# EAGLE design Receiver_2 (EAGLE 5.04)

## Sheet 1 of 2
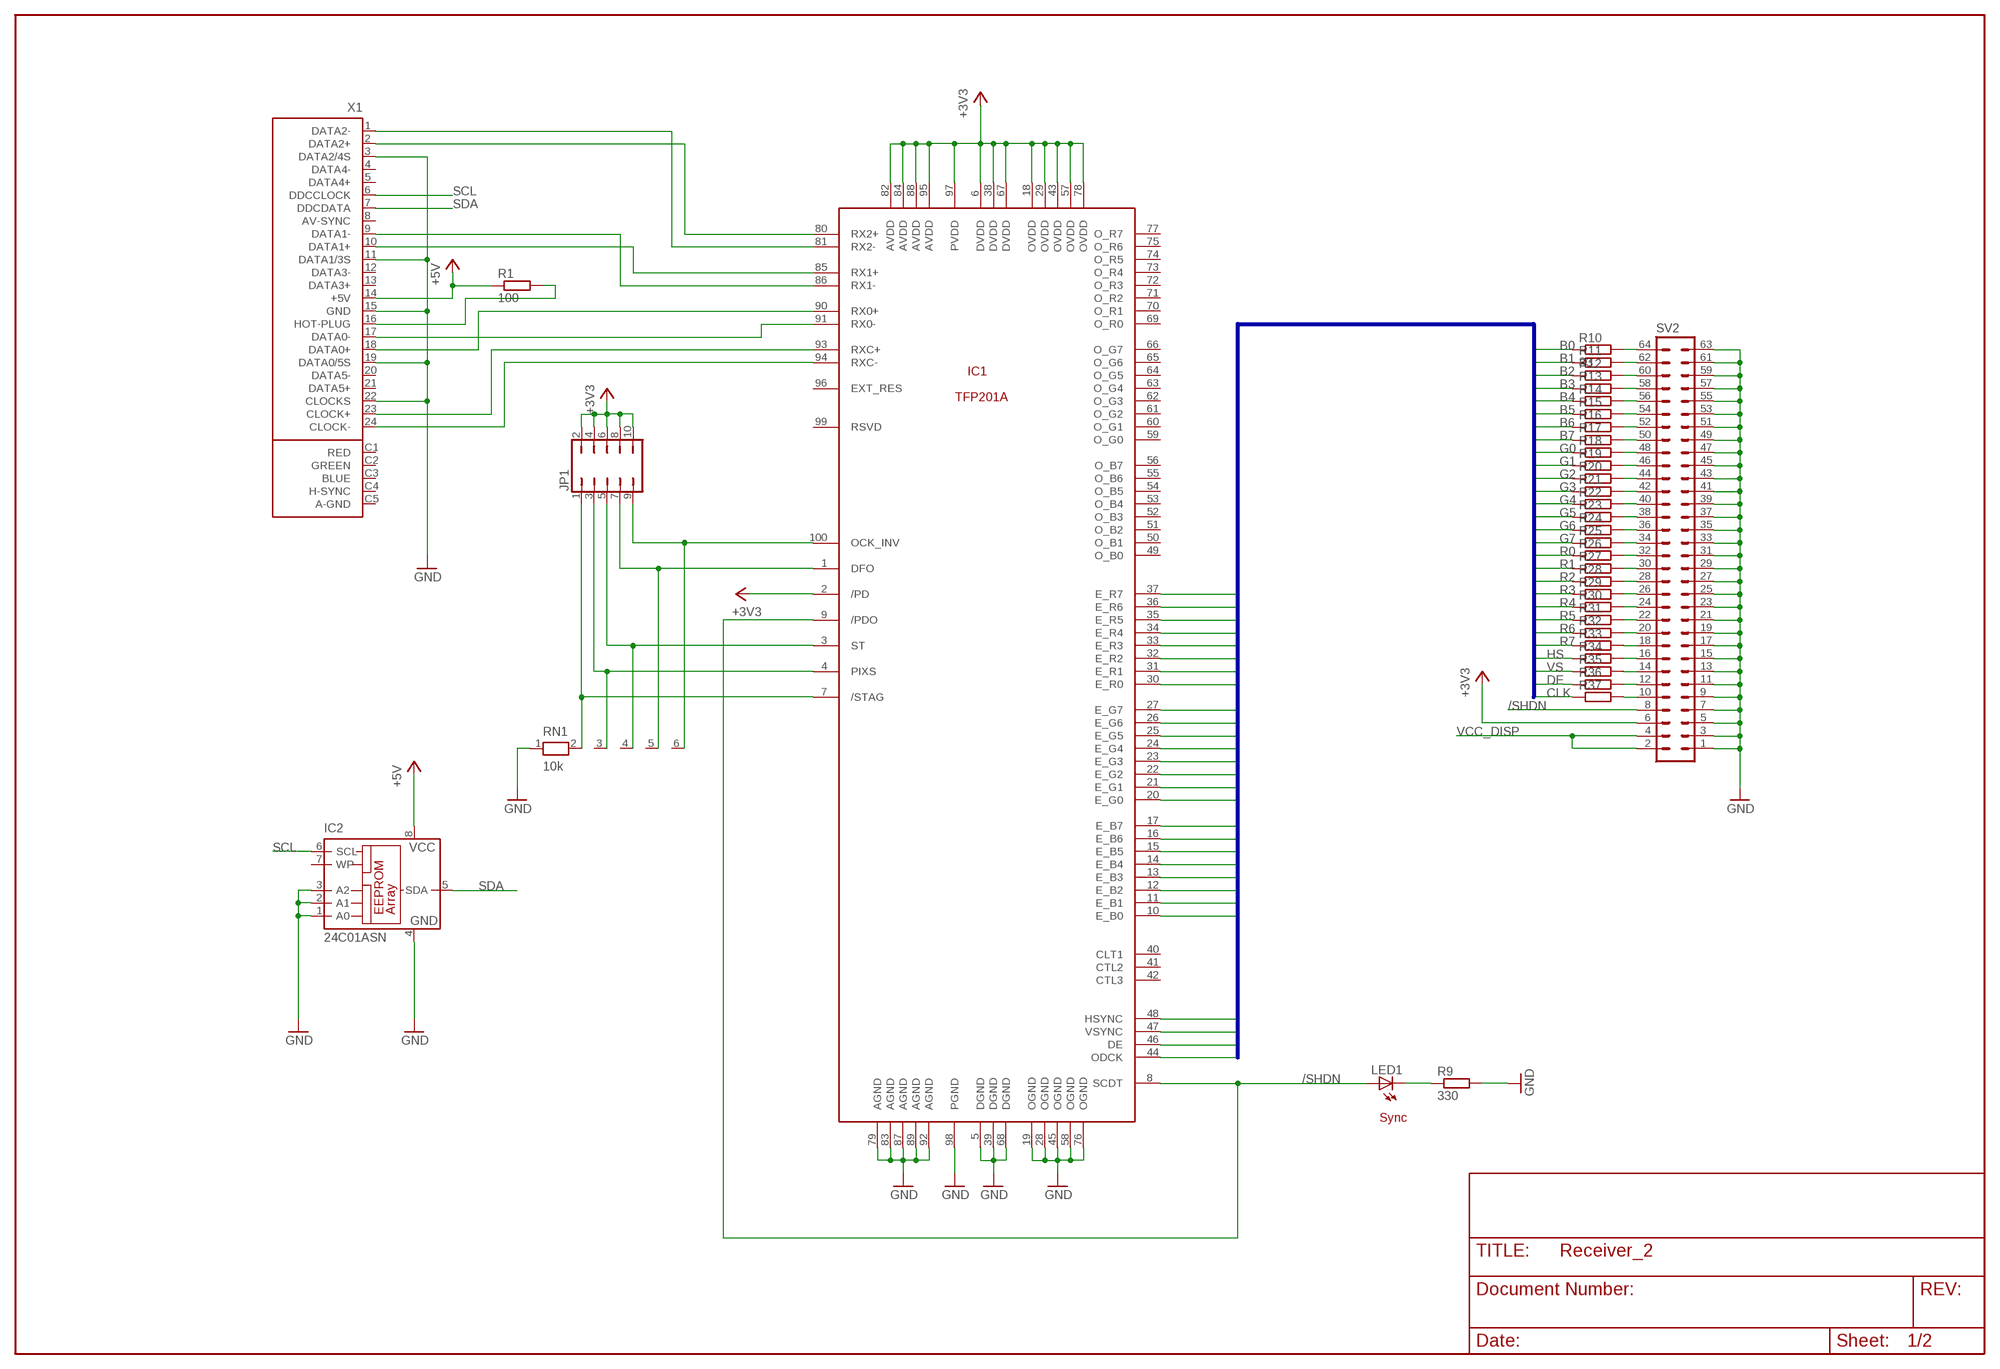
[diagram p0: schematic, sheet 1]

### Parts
IC1  TFP201ATQ100  [TQ100]
IC2  24C01ASN  [SO-08]
JP1  JP5Q  [JP5Q]
LED1  LEDCHIP-LED0805  [CHIP-LED0805]
R1  100  R-EU_R0805  [R0805]
R9  330  R-EU_R0805  [R0805]
R10  33  R-EU_R0805  [R0805]
R11  R-EU_R0805  [R0805]
R12  R-EU_R0805  [R0805]
R13  R-EU_R0805  [R0805]
R14  R-EU_R0805  [R0805]
R15  R-EU_R0805  [R0805]
R16  R-EU_R0805  [R0805]
R17  R-EU_R0805  [R0805]
R18  R-EU_R0805  [R0805]
R19  R-EU_R0805  [R0805]
R20  R-EU_R0805  [R0805]
R21  R-EU_R0805  [R0805]
R22  R-EU_R0805  [R0805]
R23  R-EU_R0805  [R0805]
R24  R-EU_R0805  [R0805]
R25  R-EU_R0805  [R0805]
R26  R-EU_R0805  [R0805]
R27  R-EU_R0805  [R0805]
R28  R-EU_R0805  [R0805]
R29  R-EU_R0805  [R0805]
R30  R-EU_R0805  [R0805]
R31  R-EU_R0805  [R0805]
R32  R-EU_R0805  [R0805]
R33  R-EU_R0805  [R0805]
R34  R-EU_R0805  [R0805]
R35  R-EU_R0805  [R0805]
R36  R-EU_R0805  [R0805]
R37  R-EU_R0805  [R0805]
RN1  10k  RN05  [RN-6]
SV2  ML64  [ML64]
X1  DVI-I-R  [DVI-I-R]

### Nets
+3V3: IC1.2(/PD) IC1.6(DVDD) IC1.18(OVDD) IC1.29(OVDD) IC1.38(DVDD) IC1.43(OVDD) IC1.57(OVDD) IC1.67(DVDD) IC1.78(OVDD) IC1.82(AVDD) IC1.84(AVDD) IC1.88(AVDD) IC1.95(AVDD) IC1.97(PVDD) JP1.2 JP1.4 JP1.6 JP1.8 JP1.10 SV2.6 ; also sheet 2
+5V: IC2.8(VCC) R1.1 X1.14(+5V)
/SHDN: IC1.8(SCDT) IC1.9(/PDO) LED1.A SV2.8 ; also sheet 2
B0: IC1.10(E_B0) R10.1
B1: IC1.11(E_B1) R11.1
B2: IC1.12(E_B2) R12.1
B3: IC1.13(E_B3) R13.1
B4: IC1.14(E_B4) R14.1
B5: IC1.15(E_B5) R15.1
B6: IC1.16(E_B6) R16.1
B7: IC1.17(E_B7) R17.1
CLK: IC1.44(ODCK) R37.1
DE: IC1.46(DE) R36.1
G0: IC1.20(E_G0) R18.1
G1: IC1.21(E_G1) R19.1
G2: IC1.22(E_G2) R20.1
G3: IC1.23(E_G3) R21.1
G4: IC1.24(E_G4) R22.1
G5: IC1.25(E_G5) R23.1
G6: IC1.26(E_G6) R24.1
G7: IC1.27(E_G7) R25.1
GND: IC1.5(DGND) IC1.19(OGND) IC1.28(OGND) IC1.39(DGND) IC1.45(OGND) IC1.58(OGND) IC1.68(DGND) IC1.76(OGND) IC1.79(AGND) IC1.83(AGND) IC1.87(AGND) IC1.89(AGND) IC1.92(AGND) IC1.98(PGND) IC2.1(A0) IC2.2(A1) IC2.3(A2) IC2.4(GND) R9.2 RN1.1 SV2.1 SV2.3 SV2.5 SV2.7 SV2.9 SV2.11 SV2.13 SV2.15 SV2.17 SV2.19 SV2.21 SV2.23 SV2.25 SV2.27 SV2.29 SV2.31 SV2.33 SV2.35 SV2.37 SV2.39 SV2.41 SV2.43 SV2.45 SV2.47 SV2.49 SV2.51 SV2.53 SV2.55 SV2.57 SV2.59 SV2.61 SV2.63 X1.3(DATA2/4S) X1.11(DATA1/3S) X1.15(GND) X1.19(DATA0/5S) X1.22(CLOCKS) ; also sheet 2
HS: IC1.48(HSYNC) R34.1
N$1: IC1.94(RXC-) X1.24(CLOCK-)
N$2: IC1.93(RXC+) X1.23(CLOCK+)
N$3: IC1.90(RX0+) X1.18(DATA0+)
N$4: IC1.91(RX0-) X1.17(DATA0-)
N$5: IC1.85(RX1+) X1.10(DATA1+)
N$6: IC1.86(RX1-) X1.9(DATA1-)
N$7: IC1.80(RX2+) X1.2(DATA2+)
N$8: IC1.81(RX2-) X1.1(DATA2-)
N$9: R10.2 SV2.64
N$13: R1.2 X1.16(HOT-PLUG)
N$15: IC1.100(OCK_INV) JP1.9 RN1.6
N$16: IC1.1(DFO) JP1.7 RN1.5
N$17: IC1.3(ST) JP1.5 RN1.4
N$19: IC1.4(PIXS) JP1.3 RN1.3
N$20: IC1.7(/STAG) JP1.1 RN1.2
N$22: LED1.C R9.1
N$24: R11.2 SV2.62
N$26: R12.2 SV2.60
N$27: R13.2 SV2.58
N$28: R14.2 SV2.56
N$30: R15.2 SV2.54
N$31: R16.2 SV2.52
N$32: R17.2 SV2.50
N$33: R18.2 SV2.48
N$34: R19.2 SV2.46
N$35: R20.2 SV2.44
N$36: R21.2 SV2.42
N$37: R22.2 SV2.40
N$38: R23.2 SV2.38
N$39: R24.2 SV2.36
N$40: R25.2 SV2.34
N$41: R26.2 SV2.32
N$42: R27.2 SV2.30
N$43: R28.2 SV2.28
N$44: R29.2 SV2.26
N$45: R30.2 SV2.24
N$46: R31.2 SV2.22
N$47: R32.2 SV2.20
N$48: R33.2 SV2.18
N$49: R34.2 SV2.16
N$50: R35.2 SV2.14
N$51: R36.2 SV2.12
N$52: R37.2 SV2.10
R0: IC1.30(E_R0) R26.1
R1: IC1.31(E_R1) R27.1
R2: IC1.32(E_R2) R28.1
R3: IC1.33(E_R3) R29.1
R4: IC1.34(E_R4) R30.1
R5: IC1.35(E_R5) R31.1
R6: IC1.36(E_R6) R32.1
R7: IC1.37(E_R7) R33.1
SCL: IC2.6(SCL) X1.6(DDCCLOCK)
SDA: IC2.5(SDA) X1.7(DDCDATA)
VCC_DISP: SV2.2 SV2.4 ; also sheet 2
VS: IC1.47(VSYNC) R35.1
Unconnected: IC1.40(CLT1) IC1.41(CTL2) IC1.42(CTL3) IC1.49(O_B0) IC1.50(O_B1) IC1.51(O_B2) IC1.52(O_B3) IC1.53(O_B4) IC1.54(O_B5) IC1.55(O_B6) IC1.56(O_B7) IC1.59(O_G0) IC1.60(O_G1) IC1.61(O_G2) IC1.62(O_G3) IC1.63(O_G4) IC1.64(O_G5) IC1.65(O_G6) IC1.66(O_G7) IC1.69(O_R0) IC1.70(O_R1) IC1.71(O_R2) IC1.72(O_R3) IC1.73(O_R4) IC1.74(O_R5) IC1.75(O_R6) IC1.77(O_R7) IC1.96(EXT_RES) IC1.99(RSVD) IC2.7(WP) X1.4(DATA4-) X1.5(DATA4+) X1.8(AV-SYNC) X1.12(DATA3-) X1.13(DATA3+) X1.20(DATA5-) X1.21(DATA5+) X1.C1(RED) X1.C2(GREEN) X1.C3(BLUE) X1.C4(H-SYNC)

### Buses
R[0..7],G[0..7],B[0..7],HS,VS,DE,CLK

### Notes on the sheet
- Sync

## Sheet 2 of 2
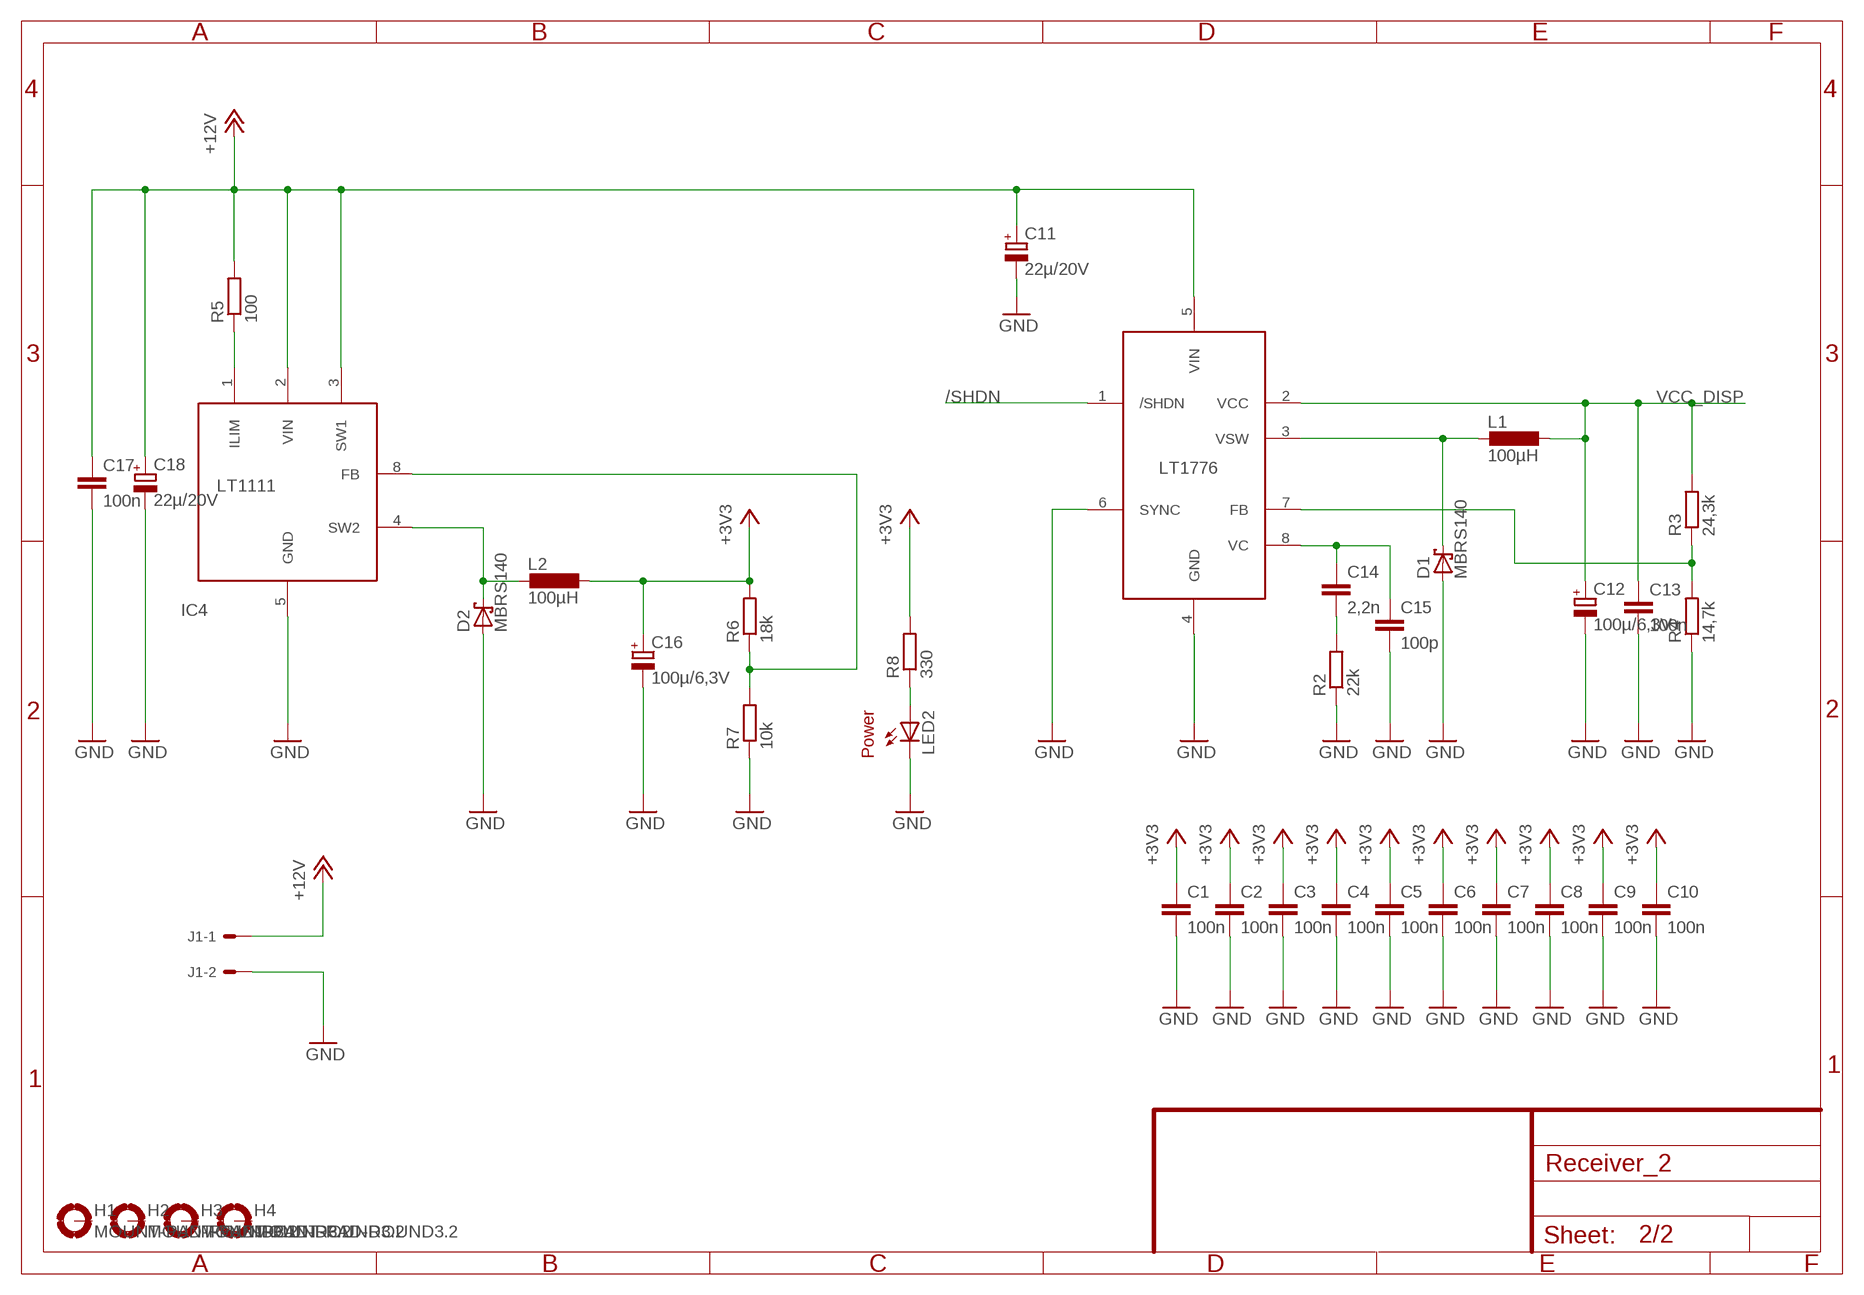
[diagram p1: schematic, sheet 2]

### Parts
C1  100n  C-EUC0805  [C0805]
C2  100n  C-EUC0805  [C0805]
C3  100n  C-EUC0805  [C0805]
C4  100n  C-EUC0805  [C0805]
C5  100n  C-EUC0805  [C0805]
C6  100n  C-EUC0805  [C0805]
C7  100n  C-EUC0805  [C0805]
C8  100n  C-EUC0805  [C0805]
C9  100n  C-EUC0805  [C0805]
C10  100n  C-EUC0805  [C0805]
C11  22µ/20V  CPOL-EUD/7343-31R  [D/7343-31R]
C12  100µ/6,3V  CPOL-EUD/7343-31R  [D/7343-31R]
C13  100n  C-EUC0805  [C0805]
C14  2,2n  C-EUC0805  [C0805]
C15  100p  C-EUC0805  [C0805]
C16  100µ/6,3V  CPOL-EUD/7343-31R  [D/7343-31R]
C17  100n  C-EUC0805  [C0805]
C18  22µ/20V  CPOL-EUD/7343-31R  [D/7343-31R]
D1  MBRS140  MBRS340  [SMC]
D2  MBRS140  MBRS340  [SMC]
H1  MOUNT-PAD-ROUND3.2  [3,2-PAD]
H2  MOUNT-PAD-ROUND3.2  [3,2-PAD]
H3  MOUNT-PAD-ROUND3.2  [3,2-PAD]
H4  MOUNT-PAD-ROUND3.2  [3,2-PAD]
IC3  LT1776CS8  [SO08]
IC4  LT1111CS  [SOIC8]
J1  22-27-2021-02  [6410-02]
L1  100µH  DO3316P  [DO3316P]
L2  100µH  DO3316P  [DO3316P]
LED2  LEDCHIP-LED0805  [CHIP-LED0805]
R2  22k  R-EU_R0805  [R0805]
R3  24,3k  R-EU_R0805  [R0805]
R4  14,7k  R-EU_R0805  [R0805]
R5  100  R-EU_R0805  [R0805]
R6  18k  R-EU_R0805  [R0805]
R7  10k  R-EU_R0805  [R0805]
R8  330  R-EU_R0805  [R0805]

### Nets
+3V3: C1.1 C2.1 C3.1 C4.1 C5.1 C6.1 C7.1 C8.1 C9.1 C10.1 C16.+ L2.2 R6.2 R8.2 ; also sheet 1
+12V: C11.+ C17.1 C18.+ IC3.5(VIN) IC4.2(VIN) IC4.3(SW1) J1.1 R5.2
/SHDN: IC3.1(/SHDN) ; also sheet 1
GND: C1.2 C2.2 C3.2 C4.2 C5.2 C6.2 C7.2 C8.2 C9.2 C10.2 C11.- C12.- C13.2 C15.2 C16.- C17.2 C18.- D1.A D2.A IC3.4(GND) IC3.6(SYNC) IC4.5(GND) J1.2 LED2.C R2.1 R4.1 R7.1 ; also sheet 1
N$10: IC3.7(FB) R3.1 R4.2
N$11: LED2.A R8.1
N$12: D1.C IC3.3(VSW) L1.1
N$14: C14.2 R2.2
N$18: IC4.1(ILIM) R5.1
N$21: C14.1 C15.1 IC3.8(VC)
N$25: D2.C IC4.4(SW2) L2.1
N$29: IC4.8(FB) R6.1 R7.2
VCC_DISP: C12.+ C13.1 IC3.2(VCC) L1.2 R3.2 ; also sheet 1
Unconnected: H1.B3,2(MOUNT) H2.B3,2(MOUNT) H3.B3,2(MOUNT) H4.B3,2(MOUNT)

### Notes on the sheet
- Power

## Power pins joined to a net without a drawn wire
A-GND: X1.C5(A-GND) X1.C6(A-GND)

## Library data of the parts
C1-C10 C13-C15 C17 = rcl:C-EU: CAPACITOR, European symbol
C11 C12 C16 C18 = rcl:CPOL-EU: POLARIZED CAPACITOR, European symbol
D1 D2 = diode:MBRS340
H1-H4 = holes:MOUNT-PAD-ROUND: MOUNTING PAD, round
IC1 = texas:TFP201A
IC2 = microchip:24C*: Serial EEPROM 1 K/2 K/4 K
IC3 = linear-technology:LT1776
IC4 = linear-technology:LT1111
J1 = con-molex_2:22-?-02: CONNECTOR
JP1 = jumper:JP5Q: JUMPER
L1 L2 = inductor-coilcraft:DO3316P: COILCRAFT
LED1 LED2 = led:LED: LED
R1-R37 = rcl:R-EU_: RESISTOR, European symbol
RN1 = resistor-net:RN05: RESISTOR NETWORK
SV2 = con-harting-ml:ML64: HARTING
X1 = con-molex:DVI-I-R: CONNECTOR MiroCross(TM)-DVI i/0 plug and receptacle connector system (scart)

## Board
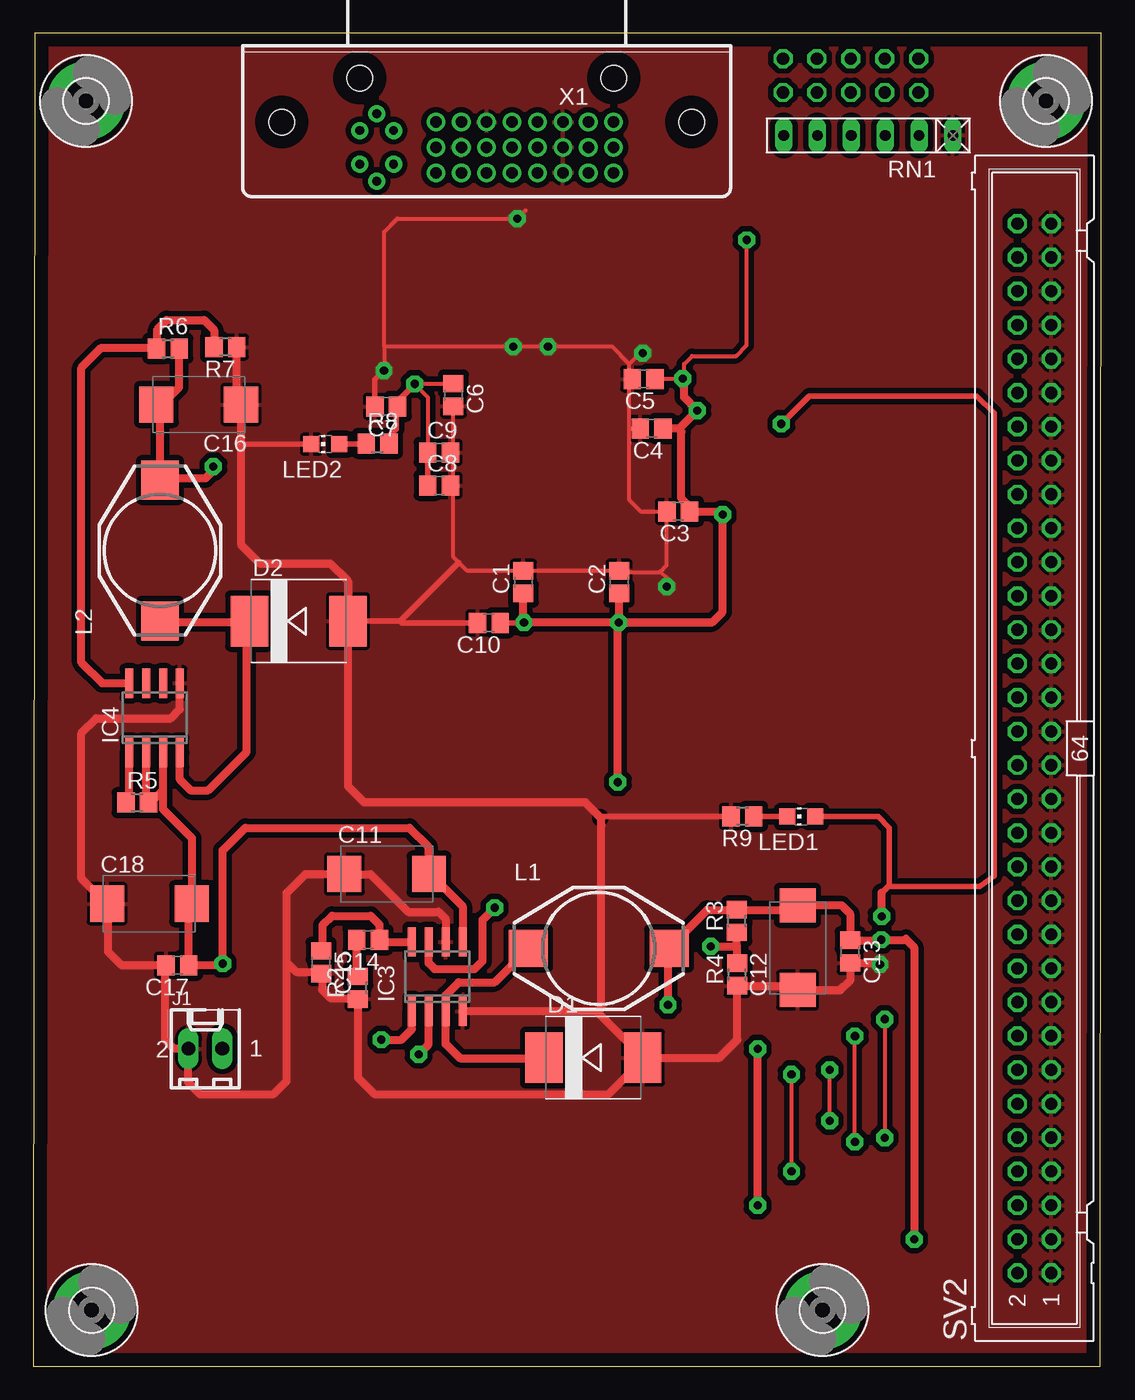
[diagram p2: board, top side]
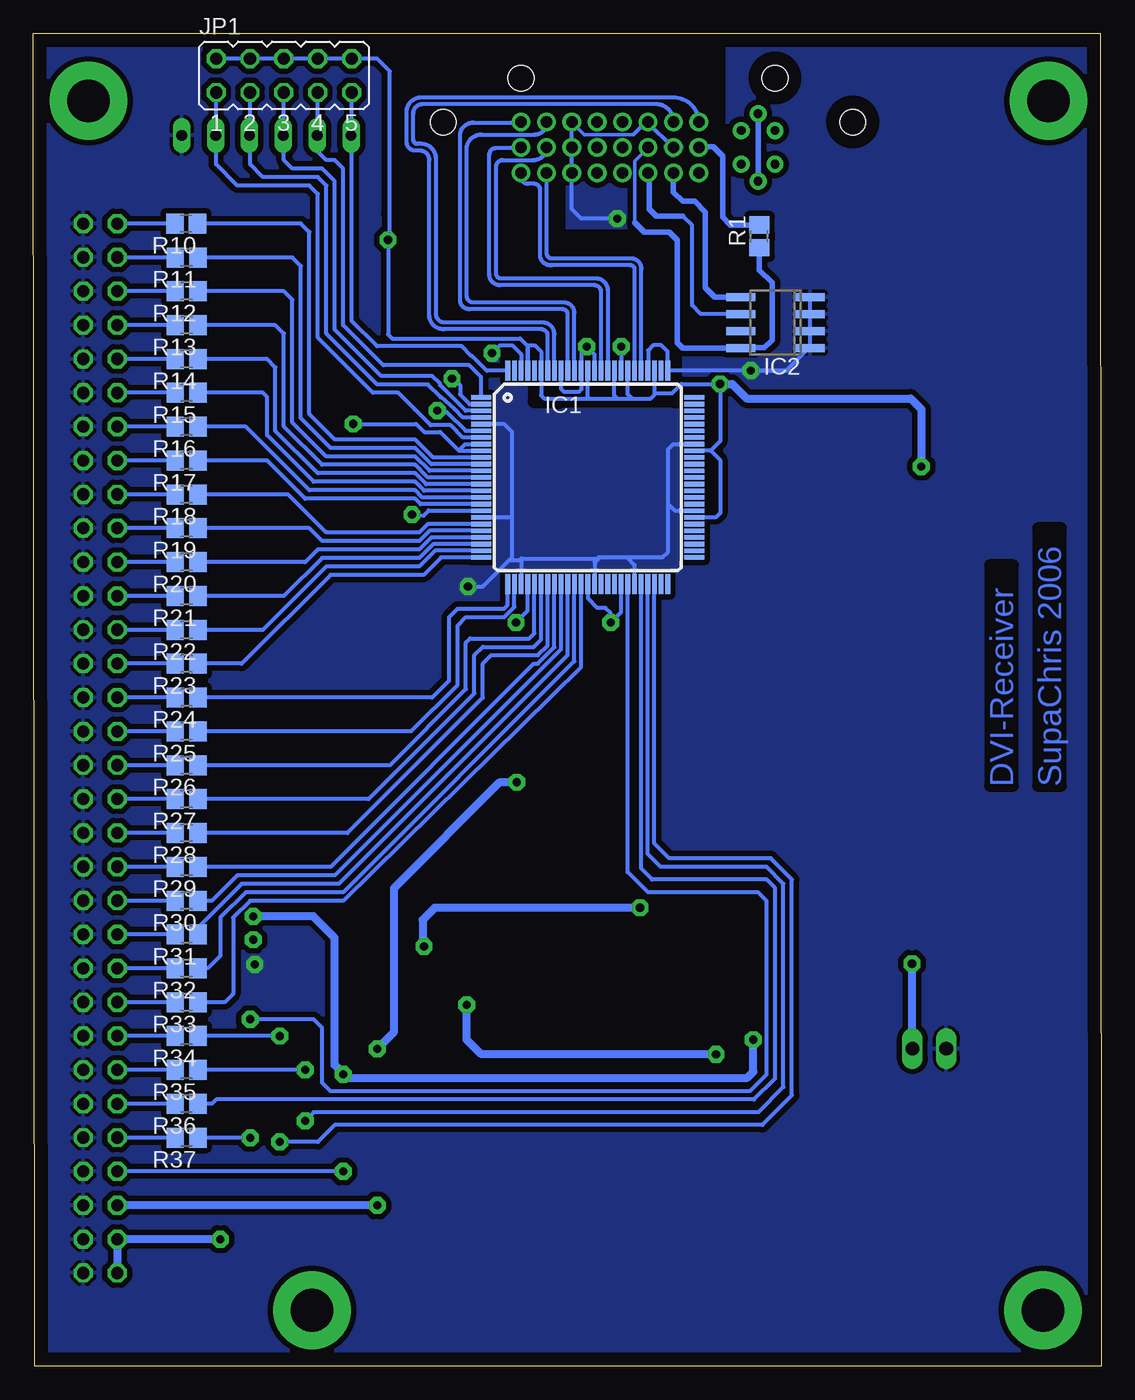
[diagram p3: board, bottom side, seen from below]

Size 80.1 x 100 mm. Coordinates in mm from the lower left corner, seen from the top.
Outline: 0.1,100 0,0 80,0 80.1,100 0.1,100
Copper layers (1+16): Top 0.035mm / dielectric 1.5mm / Bottom 0.035mm
Design rules "default": minimum track width 10mil, minimum drill 24mil, track to track 0.1mm, track to pad 0.1mm, pad to pad 0.1mm, via to via 0.2mm, smd to smd 0.1mm, copper to edge 40mil, drill to drill 8mil, minimum pad ring 10mil, minimum via ring 8mil, stop-mask expansion 4mil, vias tented up to drill 0mil, thermal gap 10mil
bRestrict: area 28.7,72.4 to 53.5,98.7; area 32,72.3 to 40.7,84.8

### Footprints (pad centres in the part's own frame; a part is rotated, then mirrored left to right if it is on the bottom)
C0805 = smd 1.3 x 1.5: 1 -0.85,0; 2 0.85,0
D/7343-31R = smd 2.55 x 2.7: + 3.175,0; - -3.175,0
SMC = smd 2.8 x 3.8: A 3.7,0; C -3.7,0
3,2-PAD = drill 3.2 pad 5.842 round: B3,2 0,0
TQ100 = smd 1.5 x 0.35: 1 -8,6; 2 -8,5.5; 3 -8,5; 4 -8,4.5; 5 -8,4; 6 -8,3.5; 7 -8,3; 8 -8,2.5; 9 -8,2; 10 -8,1.5; 11 -8,1; 12 -8,0.5; 13 -8,0; 14 -8,-0.5; 15 -8,-1; 16 -8,-1.5; 17 -8,-2; 18 -8,-2.5; 19 -8,-3; 20 -8,-3.5; 21 -8,-4; 22 -8,-4.5; 23 -8,-5; 24 -8,-5.5; 25 -8,-6; 51 8,-6; 52 8,-5.5; 53 8,-5; 54 8,-4.5; 55 8,-4; 56 8,-3.5; 57 8,-3; 58 8,-2.5; 59 8,-2; 60 8,-1.5; 61 8,-1; 62 8,-0.5; 63 8,0; 64 8,0.5; 65 8,1; 66 8,1.5; 67 8,2; 68 8,2.5; 69 8,3; 70 8,3.5; 71 8,4; 72 8,4.5; 73 8,5; 74 8,5.5; 75 8,6 | smd 0.35 x 1.5: 26 -6,-8; 27 -5.5,-8; 28 -5,-8; 29 -4.5,-8; 30 -4,-8; 31 -3.5,-8; 32 -3,-8; 33 -2.5,-8; 34 -2,-8; 35 -1.5,-8; 36 -1,-8; 37 -0.5,-8; 38 0,-8; 39 0.5,-8; 40 1,-8; 41 1.5,-8; 42 2,-8; 43 2.5,-8; 44 3,-8; 45 3.5,-8; 46 4,-8; 47 4.5,-8; 48 5,-8; 49 5.5,-8; 50 6,-8; 76 6,8; 77 5.5,8; 78 5,8; 79 4.5,8; 80 4,8; 81 3.5,8; 82 3,8; 83 2.5,8; 84 2,8; 85 1.5,8; 86 1,8; 87 0.5,8; 88 0,8; 89 -0.5,8; 90 -1,8; 91 -1.5,8; 92 -2,8; 93 -2.5,8; 94 -3,8; 95 -3.5,8; 96 -4,8; 97 -4.5,8; 98 -5,8; 99 -5.5,8; 100 -6,8
SO-08 = smd 0.6 x 2.2: 1 -1.905,-2.6; 2 -0.635,-2.6; 3 0.635,-2.6; 4 1.905,-2.6; 5 1.905,2.6; 6 0.635,2.6; 7 -0.635,2.6; 8 -1.905,2.6
SO08 = smd 0.6 x 2.2: 1 -1.905,-2.6; 2 -0.635,-2.6; 3 0.635,-2.6; 4 1.905,-2.6; 5 1.905,2.6; 6 0.635,2.6; 7 -0.635,2.6; 8 -1.905,2.6
SOIC8 = smd 0.6 x 2.2: 1 -1.905,-2.6; 2 -0.635,-2.6; 3 0.635,-2.6; 4 1.905,-2.6; 5 1.905,2.6; 6 0.635,2.6; 7 -0.635,2.6; 8 -1.905,2.6
6410-02 = drill 1.016 long: 1 1.27,0; 2 -1.27,0
JP5Q = drill 0.914 octagon: 1 -5.08,-1.27; 2 -5.08,1.27; 3 -2.54,-1.27; 4 -2.54,1.27; 5 0,-1.27; 6 0,1.27; 7 2.54,-1.27; 8 2.54,1.27; 9 5.08,-1.27; 10 5.08,1.27
DO3316P = smd 2.92 x 2.79: 1 -5.28,0; 2 5.28,0
CHIP-LED0805 = smd 1.2 x 1.2: A 0,-1.05; C 0,1.05
R0805 = smd 1.3 x 1.5: 1 -0.85,0; 2 0.85,0
RN-6 = drill 0.813 long: 1 -6.35,0; 2 -3.81,0; 3 -1.27,0; 4 1.27,0; 5 3.81,0; 6 6.35,0
ML64 = drill 0.914 octagon: 1 -39.37,-1.27; 2 -39.37,1.27; 3 -36.83,-1.27; 4 -36.83,1.27; 5 -34.29,-1.27; 6 -34.29,1.27; 7 -31.75,-1.27; 8 -31.75,1.27; 9 -29.21,-1.27; 10 -29.21,1.27; 11 -26.67,-1.27; 12 -26.67,1.27; 13 -24.13,-1.27; 14 -24.13,1.27; 15 -21.59,-1.27; 16 -21.59,1.27; 17 -19.05,-1.27; 18 -19.05,1.27; 19 -16.51,-1.27; 20 -16.51,1.27; 21 -13.97,-1.27; 22 -13.97,1.27; 23 -11.43,-1.27; 24 -11.43,1.27; 25 -8.89,-1.27; 26 -8.89,1.27; 27 -6.35,-1.27; 28 -6.35,1.27; 29 -3.81,-1.27; 30 -3.81,1.27; 31 -1.27,-1.27; 32 -1.27,1.27; 33 1.27,-1.27; 34 1.27,1.27; 35 3.81,-1.27; 36 3.81,1.27; 37 6.35,-1.27; 38 6.35,1.27; 39 8.89,-1.27; 40 8.89,1.27; 41 11.43,-1.27; 42 11.43,1.27; 43 13.97,-1.27; 44 13.97,1.27; 45 16.51,-1.27; 46 16.51,1.27; 47 19.05,-1.27; 48 19.05,1.27; 49 21.59,-1.27; 50 21.59,1.27; 51 24.13,-1.27; 52 24.13,1.27; 53 26.67,-1.27; 54 26.67,1.27; 55 29.21,-1.27; 56 29.21,1.27; 57 31.75,-1.27; 58 31.75,1.27; 59 34.29,-1.27; 60 34.29,1.27; 61 36.83,-1.27; 62 36.83,1.27; 63 39.37,-1.27; 64 39.37,1.27
DVI-I-R = drill 0.864 pad 1.397 round: 1 -9.525,6.985; 2 -7.62,6.985; 3 -5.715,6.985; 4 -3.81,6.985; 5 -1.905,6.985; 6 0,6.985; 7 1.905,6.985; 8 3.81,6.985; 9 -9.525,5.08; 10 -7.62,5.08; 11 -5.715,5.08; 12 -3.81,5.08; 13 -1.905,5.08; 14 0,5.08; 15 1.905,5.08; 16 3.81,5.08; 17 -9.525,3.175; 18 -7.62,3.175; 19 -5.715,3.175; 20 -3.81,3.175; 21 -1.905,3.175; 22 0,3.175; 23 1.905,3.175; 24 3.81,3.175 | drill 0.66 pad 1.27 round: C1 6.985,6.35; C2 9.525,6.35; C3 6.985,3.81; C4 9.525,3.81; C5 8.255,2.54; C6 8.255,7.62 | hole 1.93: -15.367,3.175; 15.367,3.175; -9.525,-0.127; 9.525,-0.127

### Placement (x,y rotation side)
C1  36.75,58.83 90 top
C2  43.94,58.83 90 top
C3  48.37,64.13 180 top
C4  46.37,70.35 180 top
C5  45.77,74.07 180 top
C6  31.51,72.87 270 top
C7  26.47,72.01 180 top
C8  30.43,66.07 0 top
C9  30.43,68.55 0 top
C10  34.17,55.77 180 top
C11  26.5,36.93 0 top
C12  57.33,31.4 90 top
C13  61.26,31.11 270 top
C14  25.11,32 180 top
C15  21.58,30.31 270 top
C16  12.4,72.16 180 top
C17  10.81,30.08 180 top
C18  8.7,34.7 0 top
D1  42,23.15 0 top
D2  19.9,55.9 0 top
H1  3.96,94.93 0 top
H2  75.96,94.93 0 top
H3  4.38,4.2 0 top
H4  59.2,4.2 0 top
IC1  38.52,66.68 0 bottom
IC2  24.45,78.3 90 bottom
IC3  30.29,29.23 0 top
IC4  9.09,48.64 0 top
J1  12.9,23.82 0 top
JP1  61.31,96.83 0 bottom
L1  42.4,31.35 0 top
L2  9.5,61.2 90 top
LED1  57.61,41.23 90 top
LED2  21.91,69.18 90 top
R1  25.65,84.77 90 bottom
R2  24.34,28.39 90 top
R3  52.76,33.39 90 top
R4  52.78,29.39 90 top
R5  7.79,42.28 0 top
R6  10.09,76.36 0 top
R7  14.41,76.46 180 top
R8  25.82,69.23 0 top
R9  53.18,41.26 180 top
R10  68.64,85.73 180 bottom
R11  68.61,83.19 180 bottom
R12  68.61,80.64 180 bottom
R13  68.61,78.11 180 bottom
R14  68.61,75.56 180 bottom
R15  68.61,73.03 180 bottom
R16  68.61,70.48 180 bottom
R17  68.61,67.94 180 bottom
R18  68.61,65.41 180 bottom
R19  68.61,62.87 180 bottom
R20  68.61,60.33 180 bottom
R21  68.61,57.78 180 bottom
R22  68.61,55.24 180 bottom
R23  68.61,52.7 180 bottom
R24  68.61,50.16 180 bottom
R25  68.61,47.62 180 bottom
R26  68.61,45.09 180 bottom
R27  68.61,42.55 180 bottom
R28  68.61,40.01 180 bottom
R29  68.61,37.47 180 bottom
R30  68.61,34.92 180 bottom
R31  68.61,32.38 180 bottom
R32  68.61,29.84 180 bottom
R33  68.61,27.3 180 bottom
R34  68.61,24.77 180 bottom
R35  68.61,22.23 180 bottom
R36  68.61,19.68 180 bottom
R37  68.61,17.14 180 bottom
RN1  62.62,92.34 180 top
SV2  75.08,46.36 90 top
X1  34,96.52 180 top

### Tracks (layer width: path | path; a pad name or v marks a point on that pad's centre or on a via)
+3V3  (via drill 0.61 pad 1.27)
  Top 0.305: 36.7,55.8 v36.8,55.8 36.75,55.85 | v53.5,84.5 53.5,76.6 52.7,75.8 49.4,75.8 48.8,75.2 48.8,74.1 | v43.9,55.8 43.94,55.84 | 49.5,64.2 v51.7,63.88 51.7,64.1 | 49.2,64.1 C3.1 | 48.8,74.1 v48.7,74.1 | 48.77,74.07 C5.1 | 48.77,74.07 48.8,74.1 | C9.1 29.58,72.72 v28.6,73.7 28.62,73.72 C6.1 | 48.45,70.35 48.4,70.35 48.4,70.3 48.6,70.1 | 48.77,74.07 48.77,74.03 48.8,74 | 48.8,74.1 48.7,74
  Top 0.406: v28.6,73.7 27.32,72.42 C7.1 27.21,72.01 27.2,72 27.2,70.3 26.67,69.77 R8.2 | C10.1 36.77,55.77 v36.8,55.8 | 29.55,68.55 29.5,68.6 | C9.1 29.55,68.55 | C8.1 29.58,68.52 29.55,68.55
  Top 0.61: v36.8,55.8 v43.9,55.8 50.9,55.8 | 49.5,64.2 48.6,65.1 48.6,70.1 | 50.9,55.8 51.7,56.6 51.7,64.1 49.2,64.1 | 36.75,55.85 C1.1 | 43.94,55.84 C2.1 | 48.4,70.35 C4.1 | 48.45,70.35 v49.8,71.7 48.8,72.7 48.8,74 | C16.+ 8.96,72.16 8.9,72.1 9.25,71.75 | 9.5,66.5 9.5,71.5 9.25,71.75 | R6.2 10.94,73.44 9.25,71.75 | v13.5,67.5 13.5,67.2 12.9,66.6 9.6,66.6 9.5,66.5 | 9.5,66.5 L2.2 | 43.84,55.8 50.9,55.8 | 43.84,55.8 43.84,55.88 | v43.84,43.81 43.84,55.8 | v54.32,12.06 v54.32,23.81 | 74.01,12.06 74,12.07 SV2.6
  Bottom 0.305: IC1.18 46.78,64.18 46.8,64.2 50.45,64.2 50.83,63.82 v51.7,63.88 | IC1.38 38.5,58.7 38.5,57.6 37.8,56.9 37.2,56.9 36.8,56.5 v36.8,55.8 36.02,56.58 IC1.43 | IC1.29 43.02,56.68 v43.9,55.8 | IC1.2 47.38,72.18 48.1,72.9 48.1,73.6 48.6,74.1 | 48.6,74.1 48.7,74.2 | 48.6,74.1 48.7,74 v48.7,74.1 | IC1.82 35.52,72.92 35.2,72.6 | 35.2,72.6 33.8,72.6 33.5,72.9 33.5,73 | IC1.78 33.52,74.62 33.5,74.6 33.5,73 | IC1.84 36.52,72.82 36.3,72.6 | 36.3,72.6 35.2,72.6 | IC1.88 38.52,72.72 38.4,72.6 | 38.4,72.6 36.3,72.6 | 38.4,72.6 41.8,72.6 42.02,72.82 IC1.95 42.02,76.12 42.5,76.6 43,76.6 43.02,76.58 IC1.97 43.02,76.52 43.6,77.1 53.2,77.1 53.5,77.4 53.5,84.4 53.55,84.45 v53.5,84.5 53.41,84.5 53.37,84.45 53.37,97.16 54.31,98.1 JP1.10 | 33.5,73 32.2,73 31.5,73.7 v28.6,73.7 28.6,69.4 29.3,68.7 | IC1.67 29.32,68.68 29.3,68.7 | IC1.57 28.92,63.68 28.6,64 28.6,68 29.3,68.7 | IC1.6 47.68,70.18 49.1,71.6 49.8,71.6 v49.8,71.7 | JP1.4 JP1.2 | JP1.4 | JP1.6 JP1.4 | JP1.6 | JP1.8 58.45,97.79 | JP1.8 JP1.6 | JP1.10 JP1.8 | JP1.10
  Bottom 0.61: v28.6,73.7 27.7,73.7 26.6,72.6 14.3,72.6 13.5,71.8 v13.5,67.5 | v43.84,43.81 45.11,43.81 53.05,35.88 53.05,25.08 v54.32,23.81 | SV2.6 73.69,12.07 73.69,12.06 v54.32,12.06
+5V
  Bottom 0.254: 35,85.8 35,90.4 33.96,91.44
  Bottom 0.305: 33.9,91.5 33.96,91.44 X1.14 | 27.1,76.4 27.09,76.39 IC2.8
  Bottom 0.406: IC2.8 31.39,76.39 31.8,76.8 31.8,84.5 32.4,85.1 34.3,85.1 35,85.8 | R1.1 25.65,82.25 24.7,81.3 24.7,77 25.3,76.4 27.1,76.4
+12V  (via drill 0.61 pad 1.27)
  Top 0.61: IC3.5 32.2,34.51 29.7,37 29.67,36.98 C11.+ 29.63,36.93 29.6,36.9 29.6,39 28.2,40.4 15.9,40.4 14.2,38.7 14.2,30.3 | v14.2,30.2 14.2,30.3 | C18.+ 11.88,34.67 11.75,34.55 | 11.75,34.55 11.66,34.46 C17.1 14.28,30.08 14.3,30.1 14.3,30.2 14.2,30.3 | IC4.2 8.46,42.65 8.8,42.3 8.78,42.28 R5.2 8.64,42.26 8.7,42.2 9.72,43.23 | 9.72,43.23 IC4.3 | 9.72,43.23 9.72,41.77 11.9,39.6 11.9,34.6 11.8,34.5 11.75,34.55
  Bottom 0.61: J1.1 14.17,30.17 v14.2,30.2
/SHDN  (via drill 0.61 pad 1.27)
  Top 0.305: v56.86,21.91 v56.86,14.61
  Top 0.406: 63.62,35.52 64.1,36 64.2,36 | 64.2,36 70.97,36 72.07,36.78 72.07,71.5 70.77,72.8 58.2,72.8 v56.1,70.7 | LED1.A 63.37,41.23 64.2,40.4 64.2,36
  Top 0.61: IC3.1 28.38,25.29 27.6,24.5 v26.1,24.5 | v63.62,33.75 63.62,35.52
  Bottom 0.305: IC1.9 48.18,68.68 48.2,68.7 | 46.58,69.18 46.6,69.2 | 46.58,69.18 IC1.8 | 56,70.7 51.4,70.7 50.8,70.1 49.6,70.1 48.2,68.7 | 46.58,69.18 47.72,69.18 48.2,68.7 | 57.5,22.6 57.5,22.55 v56.86,21.91 | SV2.8 73.69,14.61 v56.86,14.61
  Bottom 0.61: v26.1,24.5 26.1,22.1 26.6,21.6 56.5,21.6 57.5,22.6 57.5,32.15 59.1,33.75 v63.62,33.75 | v56.1,70.7 56,70.7
A-GND
  Bottom 0.305: X1.C6 25.74,88.86 25.8,88.8
  Bottom 0.406: 25.74,88.86 X1.C5
B0
  Bottom 0.305: IC1.10 50.11,68.18 51.46,69.53 57.49,69.53 59.4,71.44 59.4,85.09 60.04,85.72 67.66,85.72 67.66,85.73 R10.1
B1
  Bottom 0.305: 67.97,83.19 R11.1 60.67,83.19 60.04,82.55 60.04,71.12 57.81,68.9 51.46,68.9 50.24,67.68 IC1.11
B2
  Bottom 0.305: IC1.12 50.38,67.18 51.46,68.26 58.13,68.26 60.67,70.8 60.67,80.01 61.3,80.64 R12.1
B3
  Bottom 0.305: IC1.13 50.52,66.68 51.46,67.63 58.45,67.63 61.3,70.48 61.3,77.47 61.94,78.11 R13.1
B4
  Bottom 0.305: IC1.14 50.65,66.18 51.46,66.99 58.77,66.99 61.94,70.17 61.94,74.93 62.57,75.56 R14.1
B5
  Bottom 0.305: IC1.15 50.78,65.68 51.46,66.36 59.08,66.36 62.57,69.85 62.57,72.71 62.89,73.03 R15.1 67.97,73.03
B6
  Bottom 0.305: 67.97,70.48 R16.1 64.16,70.48 59.4,65.72 51.46,65.72 50.92,65.18 IC1.16
B7
  Bottom 0.305: IC1.17 51.05,64.68 51.46,65.09 59.72,65.09 62.57,67.94 R17.1
CLK  (via drill 0.61 pad 1.27)
  Top 0.305: v63.84,26.04 v63.84,17.14
  Bottom 0.305: IC1.44 35.52,37.08 34,35.56 25.74,35.56 25.11,34.92 25.11,21.91 26.38,20.64 57.81,20.64 58.45,21.27 58.45,25.4 59.08,26.04 v63.84,26.04 | v63.84,17.14 R37.1
DE
  Bottom 0.305: IC1.46 34.52,37.35 33.68,36.51 25.11,36.51 24.48,35.88 24.48,21.59 26.06,20 66.39,20 66.7,19.68 R36.1
G0
  Bottom 0.305: IC1.20 50.51,63.18 51.14,62.55 58.13,62.55 60.99,65.41 R18.1
G1
  Bottom 0.305: IC1.21 50.38,62.68 51.14,61.91 58.45,61.91 59.4,62.87 R19.1
G2
  Bottom 0.305: IC1.22 50.24,62.18 51.14,61.28 58.77,61.28 59.72,60.33 R20.1
G3
  Bottom 0.305: IC1.23 50.11,61.68 51.14,60.64 58.45,60.64 61.3,57.78 R21.1
G4
  Bottom 0.305: IC1.24 49.97,61.18 51.14,60.01 58.13,60.01 62.89,55.24 R22.1
G5
  Bottom 0.305: IC1.25 49.52,60.68 50.83,59.37 57.81,59.37 64.48,52.7 R23.1 67.97,52.7
G6
  Bottom 0.305: IC1.26 44.52,57.11 44.8,56.83 48.29,56.83 48.92,56.2 48.92,51.44 50.19,50.16 R24.1 67.97,50.16
G7
  Bottom 0.305: IC1.27 44.02,56.97 44.8,56.2 47.65,56.2 48.29,55.56 48.29,51.12 51.78,47.62 R25.1 67.97,47.62
GND  (via drill 0.61 pad 1.27)
  Top 0.305: 26.3,76.5 v26.3,74.7 | 26.3,76.5 26.3,85.1 27.3,86.1 v36.3,86.1 36.9,86.7 | 43.92,59.68 C1.2 36.78,59.68 36.8,59.7 32.5,59.7 31.9,60.3 31.51,60.69 31.51,66 31.51,68.51 | 47,59.6 44,59.6 43.92,59.68 | 47,59.6 47.5,60.1 47.5,64.1 | C3.2 47.6,64.2 | C3.2 | 47.5,64.1 C3.2 | 47.5,64.1 45.6,64.1 44.7,65 44.7,69.2 | 44.7,69.2 44.7,69.3 | 44.7,74.2 44.83,74.07 C5.2 | C9.2 31.25,68.55 31.2,68.5 31.4,68.5 31.4,68.4 31.51,68.51 | 43.92,59.62 43.94,59.64 C2.2 | 43.92,59.68 43.92,59.62 | 43.92,59.62 43.9,59.6 | 26.3,76.5 v36,76.5 v38.6,76.5 43.4,76.5 44.7,75.2 | 44.7,74.2 44.7,75.2 | v45.7,76 45.5,76 44.7,75.2 | v47.5,58.5 47.5,59.2 47,59.6 | 31.51,68.51 C6.2 | 44.7,69.2 44.7,70.4 | 44.7,70.4 44.7,74.2 | C4.2 44.75,70.35 44.7,70.4
  Top 0.406: C7.2 25.62,74.02 v26.3,74.7 | D2.A 27.5,55.9 | 27.5,55.9 31.9,60.3 | C10.2 27.63,55.77 27.5,55.9 | 15.6,69.18 15.6,69.2 15.7,69.2 15.7,69.18 LED2.C | 42.55,41.15 42.6,41.15 42.6,41.26 | 42.6,40.6 42.5,40.6 42.5,41.26 R9.2
  Top 0.61: 45.75,23.15 45.8,23.1 | D1.A 45.75,23.15 | IC3.4 42.27,26.63 42.3,26.6 | 45.75,23.15 42.3,26.6 | D1.A 51.45,23.15 52.8,24.5 52.8,28.4 52.7,28.5 52.74,28.54 R4.1 57.16,28.54 57.48,28.23 | 57.48,28.23 57.5,28.2 | 57.48,28.23 C12.- 60.52,28.23 61.3,29 61.3,30.2 61.26,30.24 C13.2 62.74,30.26 v63.5,30.14 | 23,36.93 20.43,36.93 19,35.5 19,30.3 | 23,36.93 C11.- | 19,30.3 19.7,29.6 21.6,29.6 21.7,29.5 21.66,29.46 | 21.66,29.46 C15.2 | 21.66,29.46 21.66,28.24 22.3,27.6 24.4,27.6 R2.1 24.34,21.66 25.6,20.4 43.1,20.4 45.7,23 D1.A | IC3.6 30.92,33.58 30.4,34.1 28.1,34.1 25.3,36.9 23,36.9 23,36.93 | 5.6,34.6 5.7,34.5 5.6,34.4 5.6,31.1 6.62,30.08 C17.2 9.92,30.08 9.9,30.1 9.9,24.5 10.58,23.82 11.5,23.82 | 5.6,34.6 5.53,34.67 C18.- | 11.5,23.82 J1.2 | 19,30.3 19,21.4 18,20.4 12.5,20.4 11.6,21.3 11.6,23.7 11.5,23.8 11.5,23.82 | IC4.5 11,49.3 10.3,48.6 4.7,48.6 3.6,47.5 3.6,36.6 5.6,34.6 | C16.- 15.58,72.17 15.6,72.2 15.55,72.25 | R7.1 15.26,72.54 15.55,72.25 | 23.6,58.9 D2.A | 15.55,72.25 15.6,72.3 15.6,69.2 15.6,61.6 17,60.2 22.3,60.2 23.6,58.9 | 23.6,58.9 23.6,43.5 24.8,42.3 41.4,42.3 42.55,41.15 42.6,41.1 42.6,40.6 42.6,26.9 42.3,26.6 | 31.51,66 31.5,66 31.43,66.07 C8.2
  Bottom 0.254: 35.1,92.4 38.8,92.4 39.71,93.31
  Bottom 0.305: 34.05,93.34 34.1,93.4 | 34.05,93.34 X1.22 34.16,93.34 35.1,92.4 | X1.15 32.14,91.44 34.05,93.34 | 39.71,93.31 X1.19 X1.11 | X1.11 39.71,91.42 39.7,91.4 | X1.3 X1.11 | X1.3 39.71,89.42 39.7,89.4 | X1.3 39.71,86.81 39,86.1 v36.3,86.1 | 34,74.3 34.02,74.32 IC1.79 34.02,74.78 34,74.8 34,76.2 33.6,76.6 33,76.6 32.52,76.12 IC1.76 23.62,74.68 | IC1.45 35.02,60.12 35.6,60.7 35.7,60.7 | 35.7,60.7 37.6,60.7 37.65,60.65 | 37.65,60.65 38,60.3 38,58.7 IC1.39 | IC1.39 | 43.52,60.58 IC1.28 | 43.52,60.58 43.5,60.6 37.8,60.6 37.7,60.7 37.65,60.65 | 30.58,69.18 30.6,69.2 | 30.58,69.18 IC1.68 | IC1.58 30.6,64.18 30.6,64.2 32,64.2 32.5,64.7 | 23.62,74.68 21.9,76.4 21.9,76.39 IC2.1 IC2.2 21.84,77.67 | 21.84,77.67 21.8,77.7 | 21.84,77.67 IC2.2 IC2.3 | IC2.3 21.8,79 | IC2.4 21.9,80.2 21.85,80.15 IC2.3 | 23.62,74.68 26.28,74.68 v26.3,74.7 | IC1.83 36.02,76.48 v36,76.5 | 38.02,74.78 38,74.8 | 38.02,74.78 IC1.87 | IC1.92 40.52,73.32 40.3,73.1 39.2,73.1 39,73.3 39,74.6 | 39,74.6 39.02,74.62 IC1.89 | 38.02,74.78 38.02,75.92 v38.6,76.5 39,76.1 39,74.6 | IC1.98 43.52,75.92 44.2,76.6 45.1,76.6 v45.7,76 | 30.58,69.18 32.12,69.18 32.5,68.8 32.5,64.7 | 32.5,64.7 32.5,61.1 32.9,60.7 35.7,60.7 | 44.2,60.5 44.4,60.5 46.4,58.5 v47.5,58.5 | 44.2,60.5 43.5,60.5 43.52,60.52 43.52,60.58 | IC1.5 44.78,70.68 44.2,70.1 44.2,63.7 | 44.2,60.5 44.2,63.7 | IC1.19 44.22,63.68 44.2,63.7
  pour Top (isolate 0.406): 0.03,100.01 80.04,100.01 80.04,0 0.03,0
  pour Bottom (isolate 0.406): 0.03,100.01 80.04,100.01 80.04,0 0.03,0
HS  (via drill 0.61 pad 1.27)
  Top 0.305: v61.62,16.83 v61.62,24.77
  Bottom 0.305: IC1.48 33.52,39.21 32.41,38.1 24.79,38.1 23.2,36.51 23.2,20.32 25.43,18.1 57.49,18.1 58.77,16.83 v61.62,16.83 | v61.62,24.77 R34.1
N$1
  Bottom 0.3: IC1.94 41.52,77.32 arc-90 42,77.8 49.3,77.8 arc90 50.4,78.8 50.4,90.5 arc-90 51.1,91.2 51.4,91.2 arc90 52.1,91.8 52.1,94.1 arc90 51,95.2 32.1,95.2 arc90 30.2,93.3 arc-90 30.19,93.31 X1.24
N$2
  Bottom 0.3: IC1.93 41.02,77.42 arc-90 41.9,78.3 49.3,78.3 arc90 49.9,79 49.9,90.6 arc-90 51,91.7 51.3,91.7 arc90 51.6,92 51.6,94 arc90 50.9,94.7 33.4,94.7 arc90 32.1,93.4 arc90 32.09,93.39 X1.23
N$3
  Bottom 0.3: IC1.90 39.52,79.02 arc-90 40.3,79.8 47.1,79.8 arc90 47.6,80.3 47.6,91.3 arc90 46.5,92.4 42.5,92.4 arc-90 41.6,93.3 arc90 41.62,93.32 X1.18
N$4
  Bottom 0.3: IC1.91 40.02,78.92 arc-90 40.4,79.3 47.4,79.3 arc90 48.1,80 48.1,92.3 arc90 47.1,93.3 43.5,93.3 arc90 43.52,93.33 X1.17
N$5
  Bottom 0.254: IC1.85 37.02,74.62 37,74.6
  Bottom 0.3: 37,74.56 37,74.6 37,80.7 arc-90 37.9,81.6 45,81.6 arc90 45.4,82 45.4,89.9 arc90 44.9,90.5 42.6,90.5 arc-90 41.6,91.4 arc90 41.62,91.42 X1.10
N$6
  Bottom 0.3: IC1.86 37.52,80.62 arc-90 38,81.1 45.1,81.1 arc90 45.9,81.9 45.9,90.9 arc90 45.4,91.4 43.5,91.4 arc90 43.52,91.42 X1.9
N$7
  Bottom 0.3: IC1.80 arc-90 34.5,74.7 34.5,82.3 arc-90 35.2,83.1 41.2,83.1 arc90 41.6,83.5 41.6,89.52 arc-90 X1.2
N$8
  Bottom 0.3: IC1.81 arc-90 35,74.7 35,82.3 arc-90 35.3,82.6 41.2,82.6 arc90 42.1,83.3 42.1,88.3 arc-90 42.5,88.7 43,88.7 arc90 43.5,89.2 43.5,89.51 arc-90 X1.1
N$9
  Bottom 0.305: SV2.64 73.69,85.73 73.69,85.72 73.68,85.73 R10.2
N$10  (via drill 0.61 pad 1.27)
  Top 0.61: 52.74,30.24 52.7,30.2 | 52.74,30.24 R4.2 | 52.76,31.5 52.76,30.26 52.74,30.24 | 52.76,31.5 R3.1 | IC3.7 29.66,30.25 30.1,29.8 33.1,29.8 33.7,30.4 33.7,33.5 v34.6,34.4 | v50.8,31.5 52.76,31.5
  Bottom 0.61: v34.6,34.4 50,34.4 50.9,33.5 50.9,31.7 50.7,31.5 v50.8,31.5
N$11
  Top 0.406: R8.1 24.93,69.23 24.88,69.18 LED2.A
N$12
  Top 0.61: D1.C 38.3,23.1 32,23.1 30.92,24.18 IC3.3 30.92,27.82 31.9,28.8 34.6,28.8 37.12,31.32 L1.1
N$13
  Bottom 0.305: 30.19,91.41 30.2,91.4 | 30.19,91.41 X1.16 | 30.1,91.5 30.19,91.41
  Bottom 0.406: R1.2 27.82,85.62 28.4,86.2 28.4,90.8 29.1,91.5 30.1,91.5
N$14
  Top 0.61: R2.2 24.34,29.26 24.26,29.34 C14.2
N$15
  Bottom 0.305: IC1.100 46.08,74.68 47.2,75.8 47.25,75.8 47.97,76.52 54.32,76.52 56.23,78.42 56.23,92.39 | 56.23,92.39 RN1.6 | JP1.9 56.23,92.4 56.23,92.39
N$16
  Bottom 0.305: IC1.1 46.52,74.22 47.4,75.1 53.85,75.1 56.86,78.11 56.86,89.85 57.49,90.49 58.13,90.49 58.77,91.12 58.77,92.39 | 58.77,92.39 RN1.5 | JP1.7 58.77,92.4 58.77,92.39
N$17
  Bottom 0.305: IC1.3 47.68,71.68 49.6,73.6 49.6,73.7 50.19,74.3 54,74.3 57.49,77.79 57.49,88.9 58.45,89.85 60.67,89.85 61.3,90.49 61.3,92.08 | RN1.4 61.3,92.39 61.3,92.08 | JP1.5 61.31,92.08 61.3,92.08
N$18
  Top 0.61: R5.1 6.92,42.28 6.9,42.3 7.19,42.59 IC4.1
N$19
  Bottom 0.305: IC1.4 47.88,71.18 48.5,71.8 49.5,72.7 49.55,72.7 50.51,73.66 54.32,73.66 58.13,77.47 58.13,88.58 58.77,89.22 62.89,89.22 63.84,90.17 63.84,92.08 | RN1.3 63.84,92.39 63.84,92.08 | JP1.3 63.85,92.08 63.84,92.08
N$20
  Bottom 0.305: IC1.7 47.88,69.68 48.8,70.6 50.3,70.6 51.5,71.8 51.51,71.8 52.73,73.03 54.64,73.03 58.77,77.15 58.77,87.95 59.4,88.58 64.8,88.58 66.39,90.17 66.39,92.39 | 66.39,92.39 RN1.2 | JP1.1 66.39,92.4 66.39,92.39
N$21
  Top 0.61: IC3.8 25.77,31.83 25.7,31.9 25.8,32 C14.1 25.96,33.14 25.3,33.8 22.4,33.8 21.7,33.1 21.7,31.2 21.6,31.1 21.58,31.12 C15.1
N$22
  Top 0.406: 53.93,41.23 53.96,41.26 R9.1 | 53.93,41.23 LED1.C | 53.93,41.23 53.9,41.2
N$23
  Top 0.406: 42.5,41.1 42.5,41.2
N$24
  Bottom 0.305: SV2.62 74,83.19 74.01,83.19 R11.2
N$25
  Top 0.61: IC4.4 11,44.01 11.8,43.2 13.1,43.2 16,46.1 16,55.8 | D2.C 16.1,55.9 16,55.8 | L2.1 9.5,55.8 16,55.8
N$26
  Bottom 0.305: SV2.60 73.69,80.65 73.69,80.64 R12.2
N$27
  Bottom 0.305: SV2.58 73.69,78.11 R13.2
N$28
  Bottom 0.305: R14.2 69.24,75.56 69.25,75.57 SV2.56
N$29
  Top 0.61: IC4.8 5.16,51.24 3.6,52.8 3.6,74.9 5.1,76.4 9.3,76.4 | 9.34,76.36 9.4,76.3 | 9.34,76.36 R6.1 9.26,76.36 9.3,76.4 | 9.3,76.4 9.34,76.36 | R7.2 13.56,77.74 12.8,78.5 10,78.5 9.3,77.8 9.3,76.4
N$30
  Bottom 0.305: 73.81,72.9 74.01,72.71 | 73.81,72.9 SV2.54 | R15.2 73.69,73.03 73.81,72.9
N$31
  Bottom 0.305: SV2.52 73.69,70.49 73.69,70.48 R16.2
N$32
  Bottom 0.305: SV2.50 74,67.95 74.01,67.94 R17.2
N$33
  Bottom 0.305: SV2.48 73.69,65.41 R18.2
N$34
  Bottom 0.305: SV2.46 73.69,62.87 R19.2
N$35
  Bottom 0.305: SV2.44 73.69,60.33 R20.2
N$36
  Bottom 0.305: SV2.42 73.69,57.79 73.69,57.78 R21.2
N$37
  Bottom 0.305: SV2.40 74,55.25 74.01,55.24 R22.2
N$38
  Bottom 0.305: SV2.38 73.69,52.71 73.69,52.7 R23.2
N$39
  Bottom 0.305: SV2.36 73.69,50.17 73.69,50.16 R24.2
N$40
  Bottom 0.305: SV2.34 73.69,47.63 73.69,47.62 R25.2
N$41
  Bottom 0.305: SV2.32 74,45.09 74.01,45.09 R26.2
N$42
  Bottom 0.305: SV2.30 73.69,42.55 R27.2
N$43
  Bottom 0.305: SV2.28 73.69,40.01 R28.2
N$44
  Bottom 0.305: SV2.26 74,37.47 74.01,37.47 R29.2
N$45
  Bottom 0.305: SV2.24 74,34.93 74.01,34.92 R30.2
N$46
  Bottom 0.305: SV2.22 74,32.39 74.01,32.38 R31.2
N$47
  Bottom 0.305: SV2.20 73.69,29.85 73.69,29.84 R32.2
N$48
  Bottom 0.305: SV2.18 73.69,27.31 73.69,27.3 R33.2
N$49
  Bottom 0.305: SV2.16 73.69,24.77 R34.2
N$50
  Bottom 0.305: SV2.14 73.69,22.23 R35.2
N$51
  Bottom 0.305: SV2.12 73.69,19.69 73.69,19.68 R36.2
N$52
  Bottom 0.305: SV2.10 73.69,17.15 73.69,17.14 R37.2
R0
  Bottom 0.305: IC1.30 42.52,54.98 42.89,54.61 47.34,54.61 47.65,54.29 47.65,50.8 53.37,45.09 R26.1 67.97,45.09
R1
  Bottom 0.305: IC1.31 42.02,54.53 42.57,53.98 46.38,53.98 47.02,53.34 47.02,50.48 54.95,42.55 R27.1 67.97,42.55
R2
  Bottom 0.305: IC1.32 41.52,54.08 42.25,53.34 45.75,53.34 46.38,52.7 46.38,50.16 56.54,40.01 R28.1
R3
  Bottom 0.305: IC1.33 41.02,53.94 42.25,52.7 42.57,52.7 57.81,37.47 R29.1 67.97,37.47
R4
  Bottom 0.305: IC1.34 40.52,53.8 57.49,36.83 64.8,36.83 66.7,34.92 R30.1
R5
  Bottom 0.305: IC1.35 40.02,53.35 57.18,36.2 64.48,36.2 67.97,32.7 R31.1
R6
  Bottom 0.305: IC1.36 39.52,52.9 56.86,35.56 64.16,35.56 66.07,33.66 66.07,30.8 67.02,29.84 R32.1
R7
  Bottom 0.305: IC1.37 39.02,52.45 56.86,34.92 63.84,34.92 65.12,33.66 65.12,27.94 65.75,27.3 R33.1
SCL
  Bottom 0.305: IC2.6 30.03,78.94 30.7,79.6 30.7,85.6 31.4,86.3 | X1.6 34,89.5 33.9,89.4
  Bottom 0.406: 31.4,86.3 33.4,86.3 33.9,86.8 33.9,89.4
SDA
  Bottom 0.305: X1.7 32.16,89.53 32.2,89.5 32.1,89.4
  Bottom 0.406: IC2.5 29,80.2 29.7,80.9 29.7,86.6 30.5,87.4 31.4,87.4 32.1,88.1 32.1,89.4
VCC_DISP  (via drill 0.61 pad 1.27)
  Top 0.61: 57.33,34.67 57.3,34.7 56.84,34.24 R3.2 50.54,34.24 47.68,31.38 L1.2 47.65,31.35 47.6,31.4 v47.6,27.1 | 57.33,34.67 C12.+ | 57.33,34.67 57.4,34.6 60.6,34.6 61.26,33.94 C13.1 63.56,31.96 v63.6,32 65.37,32 65.43,32.07 66.07,31.43 v66.07,9.53 | IC3.2 29.66,24.16 v28.9,23.4
  Bottom 0.61: v28.9,23.4 46.5,23.4 47.6,24.5 v47.6,27.1 | 74,6.99 74.01,6.99 | 74,6.99 SV2.2 | 74,6.99 73.81,7.18 SV2.4 v66.07,9.53
VS  (via drill 0.61 pad 1.27)
  Top 0.305: v59.72,18.41 v59.72,22.23
  Bottom 0.305: IC1.47 34.02,38.44 33.05,37.47 25.11,37.47 23.84,36.2 23.84,20.95 25.74,19.05 59.08,19.05 v59.72,18.41 | v59.72,22.23 R35.1

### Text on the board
Bottom: SupaChris 2006 | DVI-Receiver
